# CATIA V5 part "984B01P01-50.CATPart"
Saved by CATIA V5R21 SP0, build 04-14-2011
Part number: 984B01P01-50
Bounding box of the stored display mesh (mm): x -33.4 to 33.4, y -100 to 100, z -8 to 58
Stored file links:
  C:\Users\ALI OZGUN\Desktop\alhan\984B01P01-50.CATPart
  C:\Users\ALI OZGUN\Desktop\alhan\943B01P01.CATPart
  C:\Users\ALI OZGUN\Desktop\alhan\950B01P01.CATPart
  C:\Users\ALI OZGUN\Desktop\alhan\Product1.CATProduct
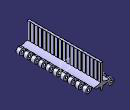
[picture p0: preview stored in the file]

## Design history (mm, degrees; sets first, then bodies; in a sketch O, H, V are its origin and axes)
Body1 (main body)
Body2
  Sketch1 on zx-plane, origin (0, 0, 0), H (-1, 0, 0), V (0, 0, 1)
    construction line L1 (25.4, 8) -> (25.4, -8)
    line L2 (25.4, -8) -> (-25.4, -8)
    construction line L3 (-25.4, -8) -> (-25.4, 8)
    line L4 (-25.4, 8) -> (25.4, 8)
    point P3 (-25.4, -8)
    arc A1 centre (25.4, 0) radius 8 from (25.4, 8) to (25.4, -8) cw
    arc A2 centre (-25.4, 0) radius 8 from (-25.4, 8) to (-25.4, -8) ccw
    point P7 (-25.4, -8)
    length L4 = 50.8
    length L3 = 16
    vertical: L1 V, L3 V
    horizontal: L2 H, L4 H
    equidistance: L1 L3 O, L2 L4 O
    tangency: A1 L2, A2 L4, A2 L2, L4 A1
    coincidence: P7 L2, P3 P7
  Pad1: profile Sketch1, direction (0, 1, 0), length 100, mirrored extent
  Sketch2 on zx-plane, origin (0, 0, 0), H (-1, 0, 0), V (0, 0, 1)
    circle A1 centre (25.4, 0) radius 3.15
    circle A2 centre (-25.4, 0) radius 3.15
  Pocket1: profile Sketch2, direction (0, -1, 0), length 204, mirrored extent
  Body3 "aramesefa"
    Sketch3 on face of Pad1 from Sketch1.L4, origin (0, 0, 8), H (1, 0, 0), V (0, 1, 0)
      line L1 (21.5, -80) -> (55.8232, -80)
      line L2 (55.8232, -80) -> (55.8232, -90.5)
      line L3 (55.8232, -90.5) -> (21.5, -90.5)
      line L4 (21.5, -90.5) -> (21.5, -80)
      reference projected line E1 (-25.4, -100) -> (25.4, -100) from edge [start face of Pad1 | face of Pad1 from Sketch1.L4]
      line L5 (-54.1233, -90) -> (-21.5, -90)
      line L6 (-21.5, -90) -> (-21.5, -100.5)
      line L7 (-21.5, -100.5) -> (-54.1233, -100.5)
      line L8 (-54.1233, -100.5) -> (-54.1233, -90)
      reference projected line E2 (-25.4, -100) -> (25.4, -100) from edge [start face of Pad1 | face of Pad1 from Sketch1.L4]
      distance L1 L3 = 10.5
      distance L3 E1 = 9.5
      distance L4 V = 21.5
      distance L5 L3 = 0.5
      distance L7 E2 = 0.5
      distance L6 L4 = 43
      horizontal: L1 H, L3 H, L5 H, L7 H
      vertical: L2 V, L4 V, L6 V, L8 V
    Pad2: profile Sketch3, direction (0, 0, 1), length 20, mirrored extent
    RectPattern1: of the body so far, direction 1 instances 10, spacing 20, along yz-plane
  Remove1: tool Body3
  Body4 "ALTBOSLUK"
    Sketch4 on zx-plane, origin (0, 0, 0), H (-1, 0, 0), V (0, 0, 1)
      line L1 (48.9583, 0) -> (33.4, 0)
      arc A1 centre (25.4, 0) radius 8 from (17.4, 0) to (33.4, 0) ccw
      line L2 (17.4, 0) -> (17.4, 0.2)
      arc A2 centre (15.4, 0.2) radius 2 from (17.4, 0.2) to (15.4, 2.2) ccw
      line L3 (15.4, 2.2) -> (5.5215, 2.2)
      arc A3 centre (5.5215, 0.2) radius 2 from (5.5215, 2.2) to (3.5325, 0.4091) ccw
      line L4 (3.5325, 0.4091) -> (2.9836, -4.8136)
      arc A4 centre (0, -4.4996) radius 3 from (-2.9836, -4.8136) to (2.9836, -4.8136) ccw
      line L5 (-2.9836, -4.8136) -> (-3.5325, 0.4091)
      arc A5 centre (-5.5215, 0.2) radius 2 from (-3.5325, 0.4091) to (-5.5215, 2.2) ccw
      line L6 (-5.5215, 2.2) -> (-15.4, 2.2)
      arc A6 centre (-15.4, 0.2) radius 2 from (-15.4, 2.2) to (-17.4, 0.2) ccw
      line L7 (-17.4, 0.2) -> (-17.4, 0)
      arc A7 centre (-25.4, 0) radius 8 from (-33.4, 0) to (-17.4, 0) ccw
      line L8 (-33.4, 0) -> (-46.3888, 0)
      line L9 (-46.3888, 0) -> (-46.3888, -17.807)
      line L10 (-46.3888, -17.807) -> (48.9583, -17.807)
      line L11 (48.9583, -17.807) -> (48.9583, 0)
      vertical: L9 V, L11 V
      horizontal: L10 H
    Pad3: profile Sketch4, direction (0, 1, 0), length 215, mirrored extent
  Remove2: tool Body4
  Body5 "KALANTIBOSALTMA"
    Sketch5 on face of Pad1 from Sketch1.L4, origin (0, 0, 8), H (1, 0, 0), V (0, 1, 0)
      line L1 (10, -80) -> (55.8232, -80)
      line L2 (55.8232, -80) -> (55.8232, -90.5)
      line L3 (55.8232, -90.5) -> (10, -90.5)
      line L4 (10, -90.5) -> (10, -80)
      reference projected line E1 (-25.4, -100) -> (25.4, -100) from edge [start face of Pad1 | face of Pad1 from Sketch1.L4]
      line L5 (-54.1233, -90) -> (-10, -90)
      line L6 (-10, -90) -> (-10, -100.5)
      line L7 (-10, -100.5) -> (-54.1233, -100.5)
      line L8 (-54.1233, -100.5) -> (-54.1233, -90)
      reference projected line E2 (-25.4, -100) -> (25.4, -100) from edge [start face of Pad1 | face of Pad1 from Sketch1.L4]
      distance L1 L3 = 10.5
      distance L3 E1 = 9.5
      distance L4 V = 10
      distance L5 L3 = 0.5
      distance L7 E2 = 0.5
      distance L6 L4 = 20
      horizontal: L1 H, L3 H, L5 H, L7 H
      vertical: L2 V, L4 V, L6 V, L8 V
    Pad4: profile Sketch5, direction (0, 0, 1), length 20, mirrored extent
    RectPattern2: of the body so far, direction 1 instances 10, spacing 20, along yz-plane
    Sketch6 on zx-plane, origin (0, 0, 0), H (-1, 0, 0), V (0, 0, 1)
      line L1 (108.0577, 2.2) -> (-84.5523, 2.2)
      fix: L1
    Pocket2: profile Sketch6, direction (0, -1, 0), length 215, mirrored extent
  Remove3: tool Body5
  Body6 "aramesefa ACILARI"
    Sketch7 on face of Pad1 from Sketch1.L4, origin (0, 0, 8), H (1, 0, 0), V (0, 1, 0)
      line L1 (21.5, -80) -> (55.8232, -80)
      line L2 (55.8232, -80) -> (55.8232, -90.5)
      line L3 (55.8232, -90.5) -> (21.5, -90.5)
      line L4 (21.5, -90.5) -> (21.5, -80)
      reference projected line E1 (-25.4, -100) -> (25.4, -100) from edge [start face of Pad1 | face of Pad1 from Sketch1.L4]
      line L5 (-54.1233, -90) -> (-21.5, -90)
      line L6 (-21.5, -90) -> (-21.5, -100.5)
      line L7 (-21.5, -100.5) -> (-54.1233, -100.5)
      line L8 (-54.1233, -100.5) -> (-54.1233, -90)
      reference projected line E2 (-25.4, -100) -> (25.4, -100) from edge [start face of Pad1 | face of Pad1 from Sketch1.L4]
      distance L1 L3 = 10.5
      distance L3 E1 = 9.5
      distance L4 V = 21.5
      distance L5 L3 = 0.5
      distance L7 E2 = 0.5
      distance L6 L4 = 43
      horizontal: L1 H, L3 H, L5 H, L7 H
      vertical: L2 V, L4 V, L6 V, L8 V
    Pad5: profile Sketch7, direction (0, 0, 1), length 20, mirrored extent
    Sketch8 on zx-plane, origin (0, 0, 0), H (-1, 0, 0), V (0, 0, 1)
      line L1 (67.6223, 8) -> (-70.015, 8)
      fix: L1
    Pocket3: profile Sketch8, direction (0, -1, 0), length 215, mirrored extent
    Draft1: Angle 45, Neutral face of Pocket3 from Sketch8.L1, PullDir face of Pocket3 from Sketch8.L1, SupportToDraft face of Pad5 from Sketch7.L6
    Draft2: Angle 45, Neutral face of Pocket3 from Sketch8.L1, PullDir face of Pocket3 from Sketch8.L1, SupportToDraft face of Pad5 from Sketch7.L4
    RectPattern3: of the body so far, direction 1 instances 10, spacing 20, along yz-plane
  Remove4: tool Body6
  Sketch9 on zx-plane, origin (0, 0, 0), H (-1, 0, 0), V (0, 0, 1)
    line L1 (0, 72) -> (0, 6.9718)
    point P1 (0, 72)
    reference projected line E1 (-25.4, -8) -> (25.4, -8) from edge [face of Pad1 from Sketch1.L2 | end face of Pad1]
    distance P1 E1 = 80
    coincidence: P1 V
    vertical: L1 V
  Sketch10 on zx-plane, origin (0, 0, 0), H (-1, 0, 0), V (0, 0, 1)
    line L1 (0, 5) -> (0, 58)
    point P1 (0, 5)
    point P2 (0, 58)
    reference projected line E1 (25.4, 8) -> (-25.4, 8) from edge [face of Pad1 from Sketch1.L4 | end face of Pad1]
    distance P1 H = 5
    distance P2 E1 = 50
    coincidence: P1 V
    vertical: L1 V
  Pad6: profile Sketch10, direction (0, 1, 0), length 100, mirrored extent, thin wall 6
  Body7
    Pad7: profile Sketch12, direction (0, 0, -1), up to face of Pad1 from Sketch1.L4
    Fillet1: radius 1.5, on edge [face of Pad7 from Sketch12.L1 | face of Pad7 from Sketch12.L3]; edge [face of Pad7 from Sketch12.L3 | face of Pad7 from Sketch12.L2]; edge [face of Pad7 from Sketch12.L9 | face of Pad7 from Sketch12.L7]; edge [face of Pad7 from Sketch12.L8 | face of Pad7 from Sketch12.L9]
    RectPattern4: of the body so far, direction 1 instances 18, spacing 10.75, along yz-plane
  Remove5: tool Body7
  Sketch11 on face of Pad6, origin (0, -100, 0), H (1, 0, 0), V (0, 0, 1)
    projected line E1 (3, 8) -> (25.4, 8) from edge [face of Pad6 | face of Pad1]
    projected line E2 (2, 8) -> (21.5, 8) from edge [face of Pad6 | face of Pad1]
    point P1 (3, 8)
    point P2 (25.4, 8)
    projected line E3 (3, 8) -> (3, 58) from edge [face of Pad6 | face of Pad6]
    point P3 (3, 8)
    offset line E4 (2, 8) -> (2, 58) from edge [face of Pad6 | face of Pad6]
    offset line E5 (2, 8) -> (2, 12.7166) from edge [face of Pad6 | face of Pad6]
    point P5 (2, 8)
    point P6 (2, 58)
    point P7 (2, 8)
    reference projected point E6 (21.5, 8) from edge [face of Pad1 | face of Pad5 from Sketch7.L4]
    arc A1 centre (21.5, 50.6681) radius 42.6681 from (2, 12.7166) to (21.5, 8) ccw
    point P9 (21.5, 8)
    point P10 (2, 12.7166)
    point P11 (-3, 8)
    point P12 (-2, 8)
    point P13 (-25.4, 8)
    point P14 (-21.5, 8)
    point P15 (-3, 8)
    point P16 (-2, 8)
    point P17 (-2, 12.7166)
    point P18 (-2, 58)
    arc A2 centre (-21.5, 50.6681) radius 42.6681 from (-2, 12.7166) to (-21.5, 8) cw
    point P20 (-21.5, 8)
    construction line L1 (-3, 8) -> (-25.4, 8)
    line L2 (-2, 8) -> (-21.5, 8)
    construction line L3 (-2, 8) -> (-2, 58)
    line L4 (-2, 8) -> (-2, 12.7166)
    coincidence: E6 A1
    symmetry: P1 P11 V, P5 P12 V, P2 P13 V, P9 P14 V, E6 P20 V, P3 P15 V, P7 P16 V, P10 P17 V, E1 L1 V, P6 P18 V, E4 L3 V, A1 A2 V, E1 L2 V, E4 L4 V
  Pad8: profile Sketch11, direction (0, 1, 0), up to face of Pad6
  Sketch12 on face of Pad6, origin (0, 0, 58), H (1, 0, 0), V (0, 1, 0)
    point P1 (2.5, -90)
    line L1 (2.5, -90) -> (3, -90)
    line L2 (3, -92.5) -> (2.5, -92.5)
    line L3 (2.5, -92.5) -> (2.5, -90)
    point P2 (3.8393, -92.5)
    point P3 (2.5, -92.5)
    reference projected line E1 (3, -100) -> (3, 100) from edge [face of Pad6 | face of Pad6]
    reference projected line E2 (-3, -100) -> (3, -100) from edge [start face of Pad6 | face of Pad6]
    projected line E3 (3, -100) -> (3, 100) from edge [face of Pad6 | face of Pad6]
    projected line E4 (3, -94.2462) -> (3, -92.5) from edge [face of Pad6 | face of Pad6]
    projected line E5 (3, -90) -> (3, -88.3449) from edge [face of Pad6 | face of Pad6]
    point P4 (3, -100)
    point P5 (3, 100)
    line L4 (3, -88.3449) -> (6.2768, -88.3449)
    point P6 (6.2768, -88.3449)
    line L5 (6.2768, -88.3449) -> (6.2768, -94.2462)
    point P7 (6.2768, -94.2462)
    line L6 (6.2768, -94.2462) -> (3, -94.2462)
    point P8 (3, -94.2462)
    point P9 (3, -88.3449)
    point P10 (3, -92.5)
    point P11 (3, -90)
    point P12 (3, -92.5)
    point P13 (3, -90)
    point P14 (-2.5, -90)
    point P15 (-3.8393, -92.5)
    point P16 (-2.5, -92.5)
    point P17 (-3, -100)
    point P18 (-6.2768, -88.3449)
    point P19 (-6.2768, -94.2462)
    point P20 (-3, -94.2462)
    point P21 (-3, -88.3449)
    point P22 (-3, -92.5)
    point P23 (-3, -90)
    point P24 (-3, -92.5)
    point P25 (-3, -90)
    line L7 (-2.5, -90) -> (-3, -90)
    line L8 (-3, -92.5) -> (-2.5, -92.5)
    line L9 (-2.5, -92.5) -> (-2.5, -90)
    point P26 (-3, 100)
    line L10 (-3, -88.3449) -> (-6.2768, -88.3449)
    line L11 (-6.2768, -88.3449) -> (-6.2768, -94.2462)
    line L12 (-6.2768, -94.2462) -> (-3, -94.2462)
    construction line L13 (-3, -100) -> (-3, 100)
    line L14 (-3, -94.2462) -> (-3, -92.5)
    line L15 (-3, -90) -> (-3, -88.3449)
    distance L1 L2 = 2.5
    distance L3 E1 = 0.5
    distance P2 E2 = 7.5
    horizontal: L1 H, L2 H, L4 H, L6 H
    vertical: L3 V, L5 V
    coincidence: L2 P10, L1 P11, E3 P12, E3 P13
    symmetry: P1 P14 V, P2 P15 V, P3 P16 V, P4 P17 V, P6 P18 V, P7 P19 V, P8 P20 V, P9 P21 V, P10 P22 V, P11 P23 V, P12 P24 V, P13 P25 V, L1 L7 V, L2 L8 V, L3 L9 V, P5 P26 V, E3 L13 V, L4 L10 V, L5 L11 V, L6 L12 V, E3 L15 V, E3 L14 V
Body8
  Solid1: linked copy from another document
  Translate1: Direction yz-plane, Length 50.8, ToTransfor Solid1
